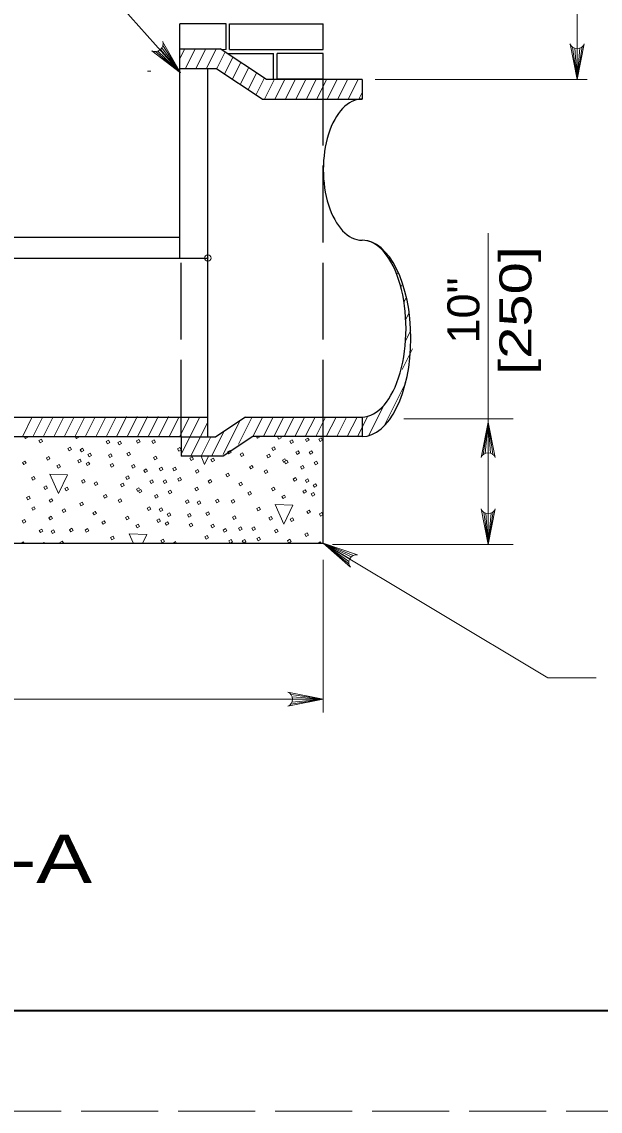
# Model space of a CAD drawing. Extents: x 750.7 to 784.7, y 860.1 to 882.1.
# Drawn here: x 757.13 to 760.02, y 860.12 to 865.55 of the extents above; entities that cross this region are included whole.
import ezdxf
from ezdxf.enums import TextEntityAlignment as Align

# ---------------------------------------------------------------- set-up
doc = ezdxf.new("R2010")
doc.units = 0
doc.header["$LTSCALE"] = 0.064
doc.header["$PDMODE"] = 32
doc.header["$PDSIZE"] = 0.032
doc.linetypes.add('LONG_DASHED', pattern=[7.5, 6, -1.5])
doc.layers.add('1', color=7, linetype='Continuous', lineweight=13)

msp = doc.modelspace()

# ---------------------------------------------------------------- linework, layer by layer
at = {"layer": '1'}
for p, q in [((759.90117, 865.26633), (759.90117, 870.88433)), ((757.83417, 865.43467), (757.92242, 865.29892)), ((759.92592, 865.42858), (759.90117, 865.26633)), ((757.79733, 865.405), (757.92242, 865.29892)), ((757.80917, 865.40725), (757.92242, 865.29892)), ((757.82183, 865.4145), (757.92242, 865.29892)), ((757.82925, 865.42325), (757.92242, 865.29892)), ((757.91908, 865.3705), (757.94325, 865.41867)), ((757.94658, 865.32075), (757.9955, 865.41867)), ((757.99883, 865.32075), (758.04783, 865.41867)), ((758.05117, 865.32075), (758.10008, 865.41867)), ((758.14442, 865.40283), (758.102, 865.31792)), ((758.14925, 865.41542), (758.12533, 865.41542)), ((758.18375, 865.37683), (758.14133, 865.29192)), ((759.87867, 865.42667), (759.90117, 865.26633)), ((759.88983, 865.42125), (759.90117, 865.26633)), ((759.9155, 865.42242), (759.90117, 865.26633)), ((759.90117, 865.41958), (759.90117, 865.26633)), ((758.22308, 865.35092), (758.18058, 865.266)), ((758.21992, 865.24), (758.26242, 865.325)), ((757.75808, 865.30742), (757.7745, 865.30742)), ((758.25925, 865.21408), (758.30167, 865.299)), ((758.341, 865.27308), (758.29858, 865.18808)), ((758.39033, 865.26717), (758.34083, 865.16817)), ((758.34992, 865.26717), (758.38683, 865.26717)), ((758.39317, 865.16817), (758.44208, 865.26608)), ((758.49442, 865.26608), (758.44542, 865.16817)), ((758.49775, 865.16817), (758.54667, 865.26608)), ((758.5995, 865.26717), (758.55, 865.16817)), ((758.65125, 865.26608), (758.60225, 865.16817)), ((758.70358, 865.26608), (758.65458, 865.16817)), ((758.70683, 865.16817), (758.75583, 865.26608)), ((758.75917, 865.16817), (758.80808, 865.26608)), ((758.89392, 865.26633), (759.95117, 865.26633)), ((758.81142, 865.16817), (758.82783, 865.20083)), ((758.97642, 864.34758), (758.98058, 864.35592)), ((759.00142, 864.29292), (759.00758, 864.30525)), ((759.02183, 864.22925), (759.0305, 864.24658)), ((759.03717, 864.15533), (759.04925, 864.17942)), ((759.04617, 864.06867), (759.06317, 864.10267)), ((759.04525, 863.96225), (759.07092, 864.01358)), ((759.02792, 863.81917), (759.07892, 863.92133)), ((758.93617, 863.53475), (759.04583, 863.75425)), ((758.86058, 863.48817), (758.936, 863.63917)), ((757.13283, 863.48367), (757.18225, 863.5825)), ((757.18517, 863.48367), (757.23458, 863.58258)), ((757.23742, 863.48367), (757.28692, 863.58275)), ((757.28975, 863.48367), (757.33925, 863.58283)), ((757.342, 863.48367), (757.39158, 863.58292)), ((757.39433, 863.48367), (757.444, 863.58308)), ((757.44658, 863.48367), (757.49633, 863.58317)), ((757.49883, 863.48367), (757.54867, 863.58325)), ((757.55117, 863.48367), (757.601, 863.58342)), ((757.60342, 863.48367), (757.65333, 863.5835)), ((757.65575, 863.48367), (757.70567, 863.58358)), ((757.708, 863.48367), (757.758, 863.58375)), ((757.76033, 863.48367), (757.81033, 863.58383)), ((757.81258, 863.48367), (757.86275, 863.584)), ((757.86492, 863.48367), (757.91392, 863.58175)), ((757.91717, 863.48367), (757.96617, 863.58175)), ((757.926, 863.39675), (758.0185, 863.58175)), ((758.21225, 863.44633), (758.28, 863.58183)), ((758.28317, 863.48375), (758.33233, 863.582)), ((758.3355, 863.48375), (758.38467, 863.58208)), ((758.38775, 863.48375), (758.437, 863.58217)), ((758.44008, 863.48375), (758.48933, 863.58233)), ((758.49233, 863.48375), (758.54167, 863.58242)), ((758.54467, 863.48375), (758.59367, 863.58175)), ((758.59692, 863.48375), (758.64592, 863.58175)), ((758.64925, 863.48375), (758.69825, 863.58175)), ((758.7015, 863.48375), (758.7505, 863.58175)), ((758.75375, 863.48375), (758.80283, 863.58175)), ((758.80608, 863.48375), (758.85708, 863.58575)), ((757.97275, 863.38575), (758.05858, 863.55733)), ((758.13417, 863.39483), (758.21842, 863.56342)), ((759.03608, 863.57283), (759.58192, 863.57283)), ((759.43267, 863.39392), (759.45742, 863.55617)), ((759.443, 863.40008), (759.45742, 863.55617)), ((759.45742, 863.40292), (759.45742, 863.55617)), ((759.46875, 863.40125), (759.45742, 863.55617)), ((759.47983, 863.39583), (759.45742, 863.55617)), ((758.02508, 863.38575), (758.074, 863.48367)), ((758.07733, 863.38575), (758.14042, 863.51192)), ((758.40675, 863.48317), (758.40783, 863.48375)), ((758.43742, 863.35533), (758.43125, 863.36617)), ((757.70858, 863.21008), (757.7025, 863.221)), ((759.44608, 863.10133), (759.45742, 862.94642)), ((759.48225, 863.10867), (759.45742, 862.94642)), ((759.47183, 863.1025), (759.45742, 862.94642)), ((759.45742, 863.09967), (759.45742, 862.94642)), ((757.66583, 862.99967), (757.68558, 862.95433)), ((757.32175, 862.95408), (757.32042, 862.95642)), ((758.16892, 862.95458), (758.16375, 862.96392)), ((758.23583, 862.95467), (758.23042, 862.96425)), ((758.46117, 862.95475), (758.45558, 862.96475)), ((758.76692, 862.87492), (758.63458, 862.95208)), ((758.76217, 862.861), (758.63458, 862.95208)), ((758.76217, 862.849), (758.63458, 862.95208)), ((758.77408, 862.88392), (758.63458, 862.95208)), ((758.78433, 862.89067), (758.63458, 862.95208)), ((758.68125, 862.94642), (759.58192, 862.94642)), ((758.63458, 862.8685), (758.63458, 862.10817)), ((756.79983, 862.17433), (758.63458, 862.17433)), ((758.47242, 862.1495), (758.63458, 862.17433)), ((758.47433, 862.19675), (758.63458, 862.17433)), ((758.47858, 862.15992), (758.63458, 862.17433)), ((758.47975, 862.18567), (758.63458, 862.17433)), ((758.48142, 862.17433), (758.63458, 862.17433))]:
    msp.add_line(p, q, dxfattribs=at)
at = {"layer": '1', "lineweight": 25}
for p, q in [((757.91908, 865.41542), (757.91908, 865.5435)), ((757.91908, 864.375), (757.91908, 865.43617)), ((757.91908, 865.41867), (758.12042, 865.41867)), ((758.35158, 865.26608), (758.12042, 865.41867)), ((758.15592, 865.39525), (758.38683, 865.39525)), ((758.38683, 865.26717), (758.38683, 865.39525)), ((758.40433, 865.26717), (758.40433, 865.39525)), ((757.91908, 865.32075), (758.09767, 865.32075)), ((758.05858, 863.48367), (758.05858, 865.32075)), ((758.32883, 865.16808), (758.09767, 865.32075)), ((758.82783, 865.26608), (758.35158, 865.26608)), ((758.6345, 865.26717), (758.40433, 865.26717)), ((758.82783, 865.26608), (758.82783, 865.16817)), ((758.32883, 865.16817), (758.82783, 865.16817)), ((754.71817, 864.4795), (757.91908, 864.4795)), ((754.71817, 864.375), (758.05858, 864.375)), ((756.86317, 863.58175), (758.05858, 863.58175)), ((758.24633, 863.58175), (758.09767, 863.48367)), ((758.24633, 863.58175), (758.82783, 863.58175)), ((758.82783, 863.58175), (758.82783, 863.48375)), ((757.926, 863.48367), (756.88958, 863.48367)), ((757.926, 863.48367), (758.09767, 863.48367)), ((757.926, 863.48367), (757.926, 863.38575)), ((758.28317, 863.48375), (758.13483, 863.38575)), ((758.82783, 863.48375), (758.28317, 863.48375)), ((758.63458, 862.95208), (758.63458, 863.48375)), ((758.13483, 863.38575), (757.926, 863.38575)), ((754.00275, 862.95208), (758.63458, 862.95208))]:
    msp.add_line(p, q, dxfattribs=at)
at = {"layer": '1', "linetype": 'LONG_DASHED', "lineweight": 25}
for p, q in [((758.63458, 863.48375), (758.6345, 865.26717)), ((757.926, 863.48367), (757.926, 864.375))]:
    msp.add_line(p, q, dxfattribs=at)
at = {"layer": '1', "linetype": 'LONG_DASHED'}
msp.add_lwpolyline([(750.65083, 860.11842), (784.65083, 860.11842), (784.65083, 882.11842), (750.65083, 882.11842)], close=True, dxfattribs=at)
at = {"layer": '1', "lineweight": 25}
for points in [[(784.15083, 860.61842), (752.65083, 860.61842), (752.65083, 881.61842)], [(758.14925, 865.41542), (758.14925, 865.5435), (757.91908, 865.5435)], [(758.16683, 865.4155), (758.16683, 865.5435), (758.63458, 865.5435)], [(758.16683, 865.4155), (758.63458, 865.4155), (758.63458, 865.5435)], [(758.6345, 865.26717), (758.6345, 865.39525), (758.40433, 865.39525)]]:
    msp.add_lwpolyline(points, dxfattribs=at)
at = {"layer": '1', "lineweight": 40}
msp.add_lwpolyline([(752.65083, 881.61842), (784.15083, 881.61842), (784.15083, 860.61842), (752.65083, 860.61842)], close=True, dxfattribs=at)
at = {"layer": '1'}
for points in [[(757.92242, 865.29892), (757.58958, 865.67383), (757.46925, 865.67383)], [(757.7795, 865.40933), (757.92242, 865.29892), (757.83292, 865.45575)], [(759.9365, 865.44342), (759.90117, 865.26633), (759.86575, 865.44342)], [(759.435, 863.10675), (759.45742, 862.94642), (759.45742, 864.49933)], [(759.422, 863.37908), (759.45742, 863.55617), (759.49283, 863.37908)], [(757.15908, 863.48367), (757.16017, 863.48183), (757.14833, 863.47508), (757.1435, 863.48367)], [(757.41392, 863.48367), (757.41525, 863.48125), (757.40342, 863.4745), (757.39825, 863.48367)], [(758.31733, 863.48375), (758.31758, 863.48325), (758.30575, 863.4765), (758.30167, 863.48375)], [(758.42208, 863.48375), (758.42492, 863.47867), (758.41308, 863.47192), (758.40675, 863.48317)], [(758.02433, 863.38575), (758.04208, 863.34508), (758.06183, 863.38575)], [(758.43125, 863.36617), (758.44317, 863.37292), (758.44633, 863.36725)], [(757.7025, 863.221), (757.71433, 863.22767), (757.71758, 863.222)], [(759.49283, 863.1235), (759.45742, 862.94642), (759.422, 863.1235)], [(757.73375, 862.95433), (757.754, 862.99592), (757.66583, 862.99967)], [(757.13, 862.954), (757.13817, 862.95867), (757.14083, 862.954)], [(757.23808, 862.954), (757.24033, 862.95533), (757.241, 862.954)], [(757.32042, 862.95642), (757.33225, 862.96317), (757.33733, 862.95408)], [(757.88808, 862.95442), (757.89783, 862.95992), (757.90092, 862.95442)], [(758.16375, 862.96392), (758.17558, 862.97058), (758.18192, 862.95933), (758.1735, 862.95458)], [(758.23042, 862.96425), (758.24225, 862.97092), (758.24858, 862.95967), (758.23967, 862.95467)], [(758.45558, 862.96475), (758.46742, 862.9715), (758.47375, 862.96025), (758.46417, 862.95475)], [(758.61308, 862.95483), (758.61975, 862.95867), (758.62192, 862.95483)], [(758.76975, 862.83233), (758.63458, 862.95208), (758.80533, 862.8935)], [(758.63458, 862.95208), (759.7555, 862.2805), (759.99625, 862.2805)], [(758.45758, 862.13892), (758.63458, 862.17433), (758.45758, 862.20975)]]:
    msp.add_lwpolyline(points, dxfattribs=at)
for points in [[(757.21583, 863.46433), (757.22775, 863.47108), (757.23408, 863.45983), (757.22225, 863.45308)], [(758.54517, 863.47008), (758.557, 863.47675), (758.56333, 863.4655), (758.5515, 863.45883)], [(758.61183, 863.47042), (758.62367, 863.47708), (758.63008, 863.46583), (758.61817, 863.45917)], [(757.36008, 863.42492), (757.37192, 863.43167), (757.37825, 863.42042), (757.36642, 863.41367)], [(757.42108, 863.41883), (757.43292, 863.42558), (757.43933, 863.41433), (757.42742, 863.40758)], [(757.55117, 863.45917), (757.563, 863.46592), (757.56933, 863.45467), (757.5575, 863.44792)], [(757.60992, 863.45475), (757.62175, 863.4615), (757.62808, 863.45025), (757.61625, 863.4435)], [(757.70183, 863.46258), (757.71375, 863.46933), (757.72008, 863.45808), (757.70817, 863.45133)], [(757.77942, 863.46092), (757.79133, 863.46758), (757.79767, 863.45633), (757.78575, 863.44967)], [(757.90717, 863.42317), (757.919, 863.42983), (757.92542, 863.41867), (757.9135, 863.41192)], [(758.37733, 863.42633), (758.38917, 863.43308), (758.3955, 863.42183), (758.38367, 863.41508)], [(758.468, 863.46092), (758.47983, 863.46758), (758.48625, 863.45633), (758.47433, 863.44967)], [(757.134, 863.35525), (757.14583, 863.362), (757.15217, 863.35075), (757.14033, 863.344)], [(757.2525, 863.37742), (757.26433, 863.38408), (757.27067, 863.37283), (757.25883, 863.36617)], [(757.40892, 863.365), (757.42075, 863.37175), (757.42708, 863.3605), (757.41525, 863.35375)], [(757.46008, 863.39483), (757.47192, 863.4015), (757.47825, 863.39025), (757.46642, 863.38358)], [(757.56225, 863.3915), (757.57408, 863.39817), (757.58042, 863.38692), (757.56858, 863.38025)], [(757.65417, 863.39933), (757.666, 863.406), (757.67233, 863.39475), (757.6605, 863.38808)], [(757.78692, 863.379), (757.79875, 863.38567), (757.80508, 863.3745), (757.79325, 863.36775)], [(757.96833, 863.37675), (757.98017, 863.3835), (757.9865, 863.37225), (757.97467, 863.3655)], [(758.07417, 863.37008), (758.086, 863.37675), (758.09233, 863.3655), (758.0805, 863.35883)], [(758.15725, 863.40858), (758.16908, 863.41525), (758.17542, 863.404), (758.16358, 863.39733)], [(758.21975, 863.39608), (758.23158, 863.40283), (758.23792, 863.39158), (758.22608, 863.38483)], [(758.35217, 863.3895), (758.364, 863.39625), (758.37033, 863.385), (758.3585, 863.37825)], [(758.44042, 863.35933), (758.45225, 863.366), (758.45858, 863.35475), (758.44675, 863.34808)], [(758.49742, 863.40675), (758.50933, 863.4135), (758.51567, 863.40225), (758.50383, 863.3955)], [(758.56417, 863.40708), (758.576, 863.41383), (758.58233, 863.40258), (758.5705, 863.39583)], [(757.3045, 863.33817), (757.31633, 863.34492), (757.32267, 863.33367), (757.31083, 863.32692)], [(757.45067, 863.35042), (757.4625, 863.35717), (757.46883, 863.34592), (757.457, 863.33917)], [(757.57067, 863.34258), (757.5825, 863.34925), (757.58883, 863.33808), (757.577, 863.33133)], [(757.678, 863.338), (757.68983, 863.34467), (757.69617, 863.33342), (757.68433, 863.32675)], [(757.73925, 863.31567), (757.75108, 863.32242), (757.75742, 863.31117), (757.74558, 863.30442)], [(757.81633, 863.32483), (757.82817, 863.33158), (757.8345, 863.32033), (757.82267, 863.31367)], [(757.88308, 863.32525), (757.89492, 863.33192), (757.90125, 863.32067), (757.88942, 863.314)], [(757.99608, 863.31275), (758.00792, 863.3195), (758.01425, 863.30825), (758.00242, 863.3015)], [(758.26583, 863.33383), (758.27767, 863.3405), (758.284, 863.32925), (758.27217, 863.32258)], [(758.33975, 863.31183), (758.35158, 863.31858), (758.35792, 863.30733), (758.34608, 863.30058)], [(758.52092, 863.33325), (758.53275, 863.34), (758.53908, 863.32875), (758.52725, 863.322)], [(758.58925, 863.3545), (758.60117, 863.36117), (758.6075, 863.34992), (758.59567, 863.34325)], [(757.17842, 863.278), (757.19025, 863.28467), (757.19658, 863.27342), (757.18475, 863.26675)], [(757.27075, 863.29733), (757.31333, 863.19992), (757.35892, 863.29367)], [(757.42842, 863.26333), (757.44025, 863.27008), (757.44658, 863.25883), (757.43475, 863.25217)], [(757.49092, 863.25092), (757.50275, 863.25767), (757.50908, 863.24642), (757.49725, 863.23967)], [(757.6485, 863.28117), (757.66033, 863.28792), (757.66667, 863.27667), (757.65483, 863.26992)], [(757.76867, 863.26158), (757.7805, 863.26833), (757.78683, 863.25708), (757.775, 863.25033)], [(757.83533, 863.26192), (757.84725, 863.26867), (757.85358, 863.25742), (757.84167, 863.25067)], [(757.90817, 863.27258), (757.92, 863.27933), (757.92633, 863.26808), (757.9145, 863.26133)], [(758.0605, 863.26242), (758.07233, 863.26917), (758.07867, 863.25792), (758.06683, 863.25117)], [(758.14792, 863.295), (758.15975, 863.30167), (758.16608, 863.29042), (758.15425, 863.28375)], [(758.21292, 863.24967), (758.22475, 863.25642), (758.23108, 863.24517), (758.21925, 863.23842)], [(758.484, 863.27242), (758.49583, 863.27917), (758.50217, 863.26792), (758.49033, 863.26117)], [(758.545, 863.26633), (758.55683, 863.273), (758.56317, 863.26183), (758.55133, 863.25508)], [(757.2395, 863.23158), (757.25133, 863.23833), (757.25775, 863.22708), (757.24583, 863.22033)], [(757.34533, 863.22483), (757.35725, 863.23158), (757.36358, 863.22033), (757.35167, 863.21358)], [(757.62333, 863.24433), (757.63517, 863.251), (757.6415, 863.23975), (757.62967, 863.23308)], [(757.71158, 863.21408), (757.72342, 863.22083), (757.72975, 863.20958), (757.71792, 863.20283)], [(757.8605, 863.20933), (757.87233, 863.216), (757.87867, 863.20475), (757.86683, 863.19808)], [(757.99392, 863.22475), (758.00575, 863.2315), (758.01208, 863.22025), (758.00025, 863.2135)], [(758.25783, 863.20275), (758.26967, 863.2095), (758.276, 863.19825), (758.26417, 863.1915)], [(758.37633, 863.22483), (758.38817, 863.23158), (758.3945, 863.22033), (758.38267, 863.21367)], [(758.53275, 863.2125), (758.54467, 863.21917), (758.551, 863.20792), (758.53908, 863.20125)], [(758.5745, 863.19792), (758.58633, 863.20467), (758.59267, 863.19342), (758.58083, 863.18667)], [(758.58392, 863.24225), (758.59575, 863.249), (758.60208, 863.23775), (758.59025, 863.231)], [(757.15425, 863.18), (757.16608, 863.18675), (757.17242, 863.1755), (757.16058, 863.16875)], [(757.26725, 863.16758), (757.27908, 863.17433), (757.28542, 863.16308), (757.27358, 863.15633)], [(757.41908, 863.14975), (757.43092, 863.1565), (757.43725, 863.14525), (757.42542, 863.1385)], [(757.53708, 863.18858), (757.54892, 863.19533), (757.55525, 863.18408), (757.54342, 863.17742)], [(757.61092, 863.16667), (757.62275, 863.17333), (757.62908, 863.16208), (757.61725, 863.15542)], [(757.79217, 863.18808), (757.804, 863.19483), (757.81033, 863.18358), (757.7985, 863.17683)], [(757.94625, 863.1615), (757.95808, 863.16817), (757.96442, 863.157), (757.95258, 863.15025)], [(758.005, 863.15708), (758.01683, 863.16375), (758.02317, 863.15258), (758.01133, 863.14583)], [(758.09692, 863.16492), (758.10875, 863.17158), (758.11508, 863.16033), (758.10325, 863.15367)], [(758.1745, 863.16317), (758.18633, 863.16992), (758.19267, 863.15867), (758.18083, 863.15192)], [(758.39458, 863.14483), (758.43717, 863.04733), (758.48275, 863.14117)], [(758.42842, 863.18567), (758.44025, 863.19242), (758.44658, 863.18117), (758.43475, 863.17442)], [(757.17933, 863.12742), (757.19125, 863.13408), (757.19758, 863.12283), (757.18575, 863.11617)], [(757.33167, 863.11725), (757.3435, 863.124), (757.34992, 863.11275), (757.338, 863.106)], [(757.48408, 863.1045), (757.49592, 863.11117), (757.50225, 863.09992), (757.49042, 863.09325)], [(757.75517, 863.12725), (757.767, 863.134), (757.77333, 863.12275), (757.7615, 863.116)], [(757.81617, 863.12117), (757.828, 863.12783), (757.83433, 863.11658), (757.8225, 863.10992)], [(757.85517, 863.09708), (757.867, 863.10383), (757.87333, 863.09258), (757.8615, 863.08583)], [(757.95725, 863.09375), (757.96908, 863.1005), (757.9755, 863.08925), (757.96358, 863.0825)], [(758.04925, 863.10158), (758.06108, 863.10833), (758.06742, 863.09708), (758.05558, 863.09033)], [(758.30225, 863.12542), (758.31408, 863.13217), (758.32042, 863.12092), (758.30858, 863.11417)], [(758.55233, 863.11083), (758.56417, 863.11758), (758.5705, 863.10633), (758.55867, 863.09958)], [(758.61483, 863.09842), (758.62667, 863.10508), (758.633, 863.09392), (758.62117, 863.08717)], [(757.13167, 863.06408), (757.1435, 863.07083), (757.14983, 863.05958), (757.138, 863.05283)], [(757.26508, 863.07958), (757.27692, 863.08633), (757.28325, 863.07508), (757.27142, 863.06833)], [(757.529, 863.05758), (757.54092, 863.06425), (757.54725, 863.053), (757.53542, 863.04633)], [(757.64758, 863.07967), (757.65942, 863.08642), (757.66575, 863.07517), (757.65392, 863.06842)], [(757.69958, 863.0405), (757.71142, 863.04717), (757.71775, 863.03592), (757.70592, 863.02925)], [(757.804, 863.06725), (757.81583, 863.074), (757.82217, 863.06275), (757.81033, 863.05608)], [(757.84575, 863.05275), (757.85758, 863.0595), (757.86392, 863.04825), (757.85208, 863.0415)], [(757.96567, 863.04483), (757.9775, 863.05158), (757.98392, 863.04033), (757.972, 863.03358)], [(758.073, 863.04025), (758.08483, 863.047), (758.09117, 863.03575), (758.07933, 863.029)], [(758.182, 863.08125), (758.19383, 863.088), (758.20017, 863.07675), (758.18833, 863.07)], [(758.36342, 863.07908), (758.37525, 863.08575), (758.38158, 863.07458), (758.36975, 863.06783)], [(758.46925, 863.07233), (758.48108, 863.07908), (758.48742, 863.06783), (758.47558, 863.06108)], [(757.21742, 863.01633), (757.22925, 863.023), (757.23558, 863.01175), (757.22375, 863.00508)], [(757.27617, 863.01192), (757.288, 863.01858), (757.29433, 863.00733), (757.2825, 863.00067)], [(757.36808, 863.01967), (757.38, 863.02642), (757.38633, 863.01517), (757.37442, 863.00842)], [(757.44567, 863.018), (757.45758, 863.02475), (757.46392, 863.0135), (757.45208, 863.00675)], [(757.57342, 862.98025), (757.58533, 862.987), (757.59167, 862.97575), (757.57983, 862.969)], [(758.04358, 862.9835), (758.05542, 862.99017), (758.06175, 862.97892), (758.04992, 862.97225)], [(758.13425, 863.018), (758.14617, 863.02475), (758.1525, 863.0135), (758.14058, 863.00675)], [(758.21142, 863.02717), (758.22325, 863.03392), (758.22958, 863.02267), (758.21775, 863.01592)], [(758.27808, 863.0275), (758.29, 863.03425), (758.29633, 863.023), (758.28442, 863.01625)], [(758.30325, 862.97492), (758.31508, 862.98158), (758.32142, 862.97033), (758.30958, 862.96367)], [(758.39117, 863.01508), (758.403, 863.02183), (758.40933, 863.01058), (758.3975, 863.00383)], [(758.543, 862.99725), (758.55483, 863.004), (758.56117, 862.99275), (758.54933, 862.986)], [(757.8235, 862.96567), (757.83533, 862.97242), (757.84167, 862.96117), (757.82983, 862.95442)]]:
    msp.add_lwpolyline(points, close=True, dxfattribs=at)
for centre, start, end in [((757.79686, 865.44335), 243.10985, 18.93597), ((759.90109, 865.45774), 202.08782, 337.91395), ((759.45749, 863.36478), 22.08782, 157.91395), ((759.45741, 863.13783), 202.08782, 337.91395), ((758.79991, 862.85572), 81.85118, 217.67731), ((758.44325, 862.17436), 292.08605, 67.91218)]:
    msp.add_arc(centre, 0.03822, start, end, dxfattribs=at)
at = {"layer": '1', "lineweight": 25}
for centre, major_axis, ratio, start_param, end_param in [((758.8278, 864.81608), (0, 0.35205), 0.549064, 0.0000001, 3.1415928), ((758.82781, 863.97389), (0, 0.49015), 0.497655, 3.1415928, 6.2831854), ((758.82781, 864.02291), (0, -0.44112), 0.497655, 0.0000001, 3.1415928)]:
    msp.add_ellipse(centre, major_axis=major_axis, ratio=ratio, start_param=start_param, end_param=end_param, dxfattribs=at)
at = {"layer": '1'}
msp.add_point((758.05858, 864.375), dxfattribs=at)

# ---------------------------------------------------------------- texts
for s, width, p in [('[250]', 1.35, (759.67342, 864.11308)), ('10"', 1.05, (759.41342, 864.11308))]:
    msp.add_text(s, height=0.16, rotation=90, dxfattribs=dict(at, width=width)).set_placement(p, align=Align.CENTER)
at = {"layer": '1', "width": 1.3}
msp.add_text('SECTION A-A', height=0.24, dxfattribs=at).set_placement((754.81458, 861.25733))

doc.saveas('drawing.dxf')
